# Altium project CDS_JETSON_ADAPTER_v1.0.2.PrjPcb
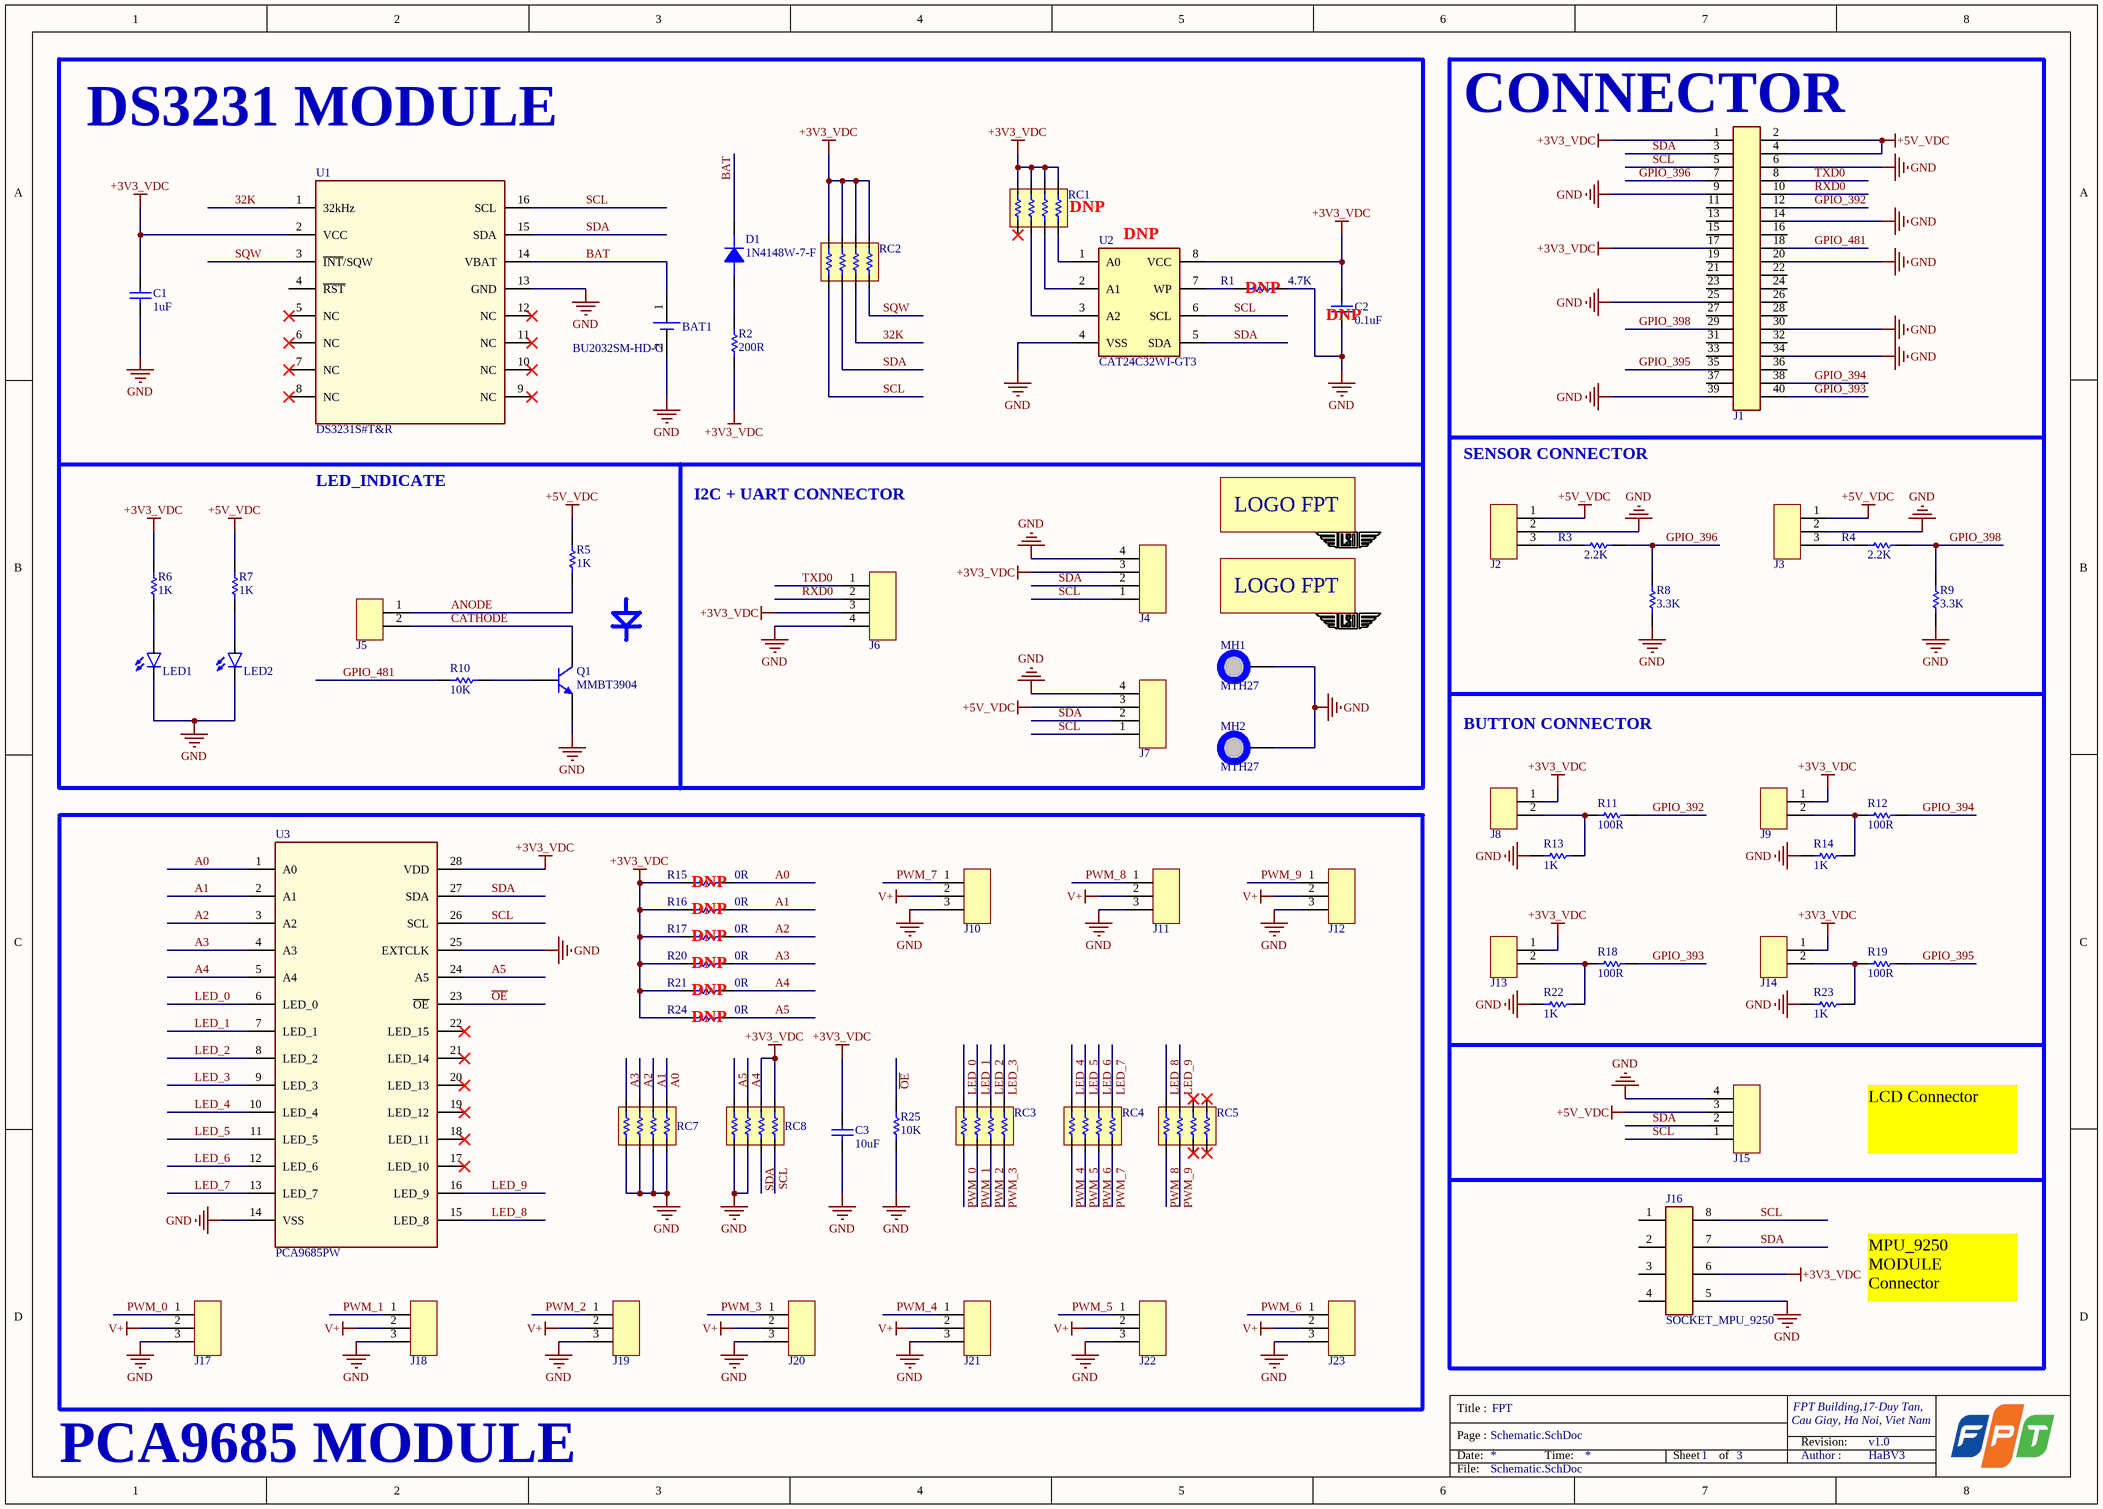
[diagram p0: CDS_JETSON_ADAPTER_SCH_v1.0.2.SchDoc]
1 sheet, 70 parts. Net scope: global (net labels, ports and power ports of the same name join across sheets).
Board file: CDS_JETSON_ADAPTER_PCB_v1.0.2.PcbDoc

## Sheet CDS_JETSON_ADAPTER_SCH_v1.0.2.SchDoc
size A3; Author: HaBV3; CompanyName: FPT CORPORATION; Address1: FPT Building,17-Duy Tan,; Address2: Cau Giay, Ha Noi, Viet Nam; Revision: v1.0; SheetNumber: 1; SheetTotal: 3; Project: FPT

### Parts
BAT1  BU2032SM-HD-G  [BU2032SM-HD-G]
C1  value 1uF  [C0603]  (hidden comment: GRM188R61A106ME69D)
C2  value 0.1uF  [C0603]  (hidden comment: GRM188R70J104KA01D)
C3  value 10uF  [C0603]  (hidden comment: GRM188R61C106KAALD)
D1  1N4148W-7-F  [DO-SOD-123]
J1  HDR_2x20  [HEADER_SOCKET_2.54MM_2x20]  (value not drawn)
J2  HDR_1x3  [B3B-XH-A(LF)(SN)]  (value not drawn)
J3  HDR_1x3  [B3B-XH-A(LF)(SN)]  (value not drawn)
J4  HDR_1x4  [B4B-XH-A(LF)(SN)]  (value not drawn)
J5  HDR_1x2  [B2B-XH-A(LF)(SN)]  (value not drawn)
J6  HDR_1x4  [B4B-XH-A(LF)(SN)]  (value not drawn)
J7  HDR_1x4  [B4B-XH-A(LF)(SN)]  (value not drawn)
J8  HDR_1x2  [B2B-XH-A(LF)(SN)]  (value not drawn)
J9  HDR_1x2  [B2B-XH-A(LF)(SN)]  (value not drawn)
J10  HDR_1x3  [PINHEAD_2.54mm_1x3]  (value not drawn)
J11  HDR_1x3  [PINHEAD_2.54mm_1x3]  (value not drawn)
J12  HDR_1x3  [PINHEAD_2.54mm_1x3]  (value not drawn)
J13  HDR_1x2  [B2B-XH-A(LF)(SN)]  (value not drawn)
J14  HDR_1x2  [B2B-XH-A(LF)(SN)]  (value not drawn)
J15  HDR_1x4  [B4B-XH-A(LF)(SN)]  (value not drawn)
J16  SOCKET_MPU_9250  [SOCKET_MPU_9250]
J17  HDR_1x3  [PINHEAD_2.54mm_1x3]  (value not drawn)
J18  HDR_1x3  [PINHEAD_2.54mm_1x3]  (value not drawn)
J19  HDR_1x3  [PINHEAD_2.54mm_1x3]  (value not drawn)
J20  HDR_1x3  [PINHEAD_2.54mm_1x3]  (value not drawn)
J21  HDR_1x3  [PINHEAD_2.54mm_1x3]  (value not drawn)
J22  HDR_1x3  [PINHEAD_2.54mm_1x3]  (value not drawn)
J23  HDR_1x3  [PINHEAD_2.54mm_1x3]  (value not drawn)
LED1  LTST-C191KRKT  [LED-SMD-0603-RED]  (value not drawn)
LED2  LTST-C191KRKT  [LED-SMD-0603-RED]  (value not drawn)
LOGO1  LOGOFPT  [LOGO_FPT]  (value not drawn)
LOGO2  LOGOFPT  [LOGO_FPT]  (value not drawn)
MH1  MTH27  [MH_5.2MMD_2.7MMD]
MH2  MTH27  [MH_5.2MMD_2.7MMD]
Q1  MMBT3904  [MMBT3904]
R1  value 4.7K  [R0603]  (hidden comment: RC0603JR-074K7L)
R2  value 200R  [R0603]  (hidden comment: RC0603JR-07200RL)
R3  value 2.2K  [R0603]  (hidden comment: RC0603FR-072K2L)
R4  value 2.2K  [R0603]  (hidden comment: RC0603FR-072K2L)
R5  value 1K  [R0603]  (hidden comment: RC0603FR-071KL)
R6  value 1K  [R0603]  (hidden comment: RC0603FR-071KL)
R7  value 1K  [R0603]  (hidden comment: RC0603FR-071KL)
R8  value 3.3K  [R0603]  (hidden comment: RC0603FR-073K3L)
R9  value 3.3K  [R0603]  (hidden comment: RC0603FR-073K3L)
R10  value 10K  [R0603]  (hidden comment: RC0603JR-0710KL)
R11  value 100R  [R0603]  (hidden comment: RC0603FR-07100RL)
R12  value 100R  [R0603]  (hidden comment: RC0603FR-07100RL)
R13  value 1K  [R0603]  (hidden comment: RC0603FR-071KL)
R14  value 1K  [R0603]  (hidden comment: RC0603FR-071KL)
R15  value 0R  [R0603]  (hidden comment: RC0603JR-070RL)
R16  value 0R  [R0603]  (hidden comment: RC0603JR-070RL)
R17  value 0R  [R0603]  (hidden comment: RC0603JR-070RL)
R18  value 100R  [R0603]  (hidden comment: RC0603FR-07100RL)
R19  value 100R  [R0603]  (hidden comment: RC0603FR-07100RL)
R20  value 0R  [R0603]  (hidden comment: RC0603JR-070RL)
R21  value 0R  [R0603]  (hidden comment: RC0603JR-070RL)
R22  value 1K  [R0603]  (hidden comment: RC0603FR-071KL)
R23  value 1K  [R0603]  (hidden comment: RC0603FR-071KL)
R24  value 0R  [R0603]  (hidden comment: RC0603JR-070RL)
R25  value 10K  [R0603]  (hidden comment: RC0603JR-0710KL)
RC1  YC164-JR-074K7L  [RC_1206]  (value not drawn)
RC2  YC164-JR-074K7L  [RC_1206]  (value not drawn)
RC3  YC164-JR-07220RL  [RC_1206]  (value not drawn)
RC4  YC164-JR-07220RL  [RC_1206]  (value not drawn)
RC5  YC164-JR-07220RL  [RC_1206]  (value not drawn)
RC7  YC164-JR-0710KL  [RC_1206]  (value not drawn)
RC8  YC164-JR-0710KL  [RC_1206]  (value not drawn)
U1  DS3231S#T&R  [SOIC127P1030X265-16N]
U2  CAT24C32WI-GT3  [SOIC127P600X175-8N]
U3  PCA9685PW  [TSOP65P640X110-28N]

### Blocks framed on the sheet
DS3231 MODULE: BAT1 C1 C2 D1 J4-J7 LED1 LED2 LOGO1 LOGO2 MH1 MH2 Q1 R1 R2 R5-R7 R10 RC1 RC2 U1 U2
CONNECTOR: J1-J3 J8 J9 J13-J16 R3 R4 R8 R9 R11-R14 R18 R19 R22 R23

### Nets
+3V3_VDC: C1.1 C2.2 C3.1 J1.1 J1.17 J4.3 J6.3 J8.1 J9.1 J13.1 J14.1 J16.6 R2.1 R6.1 R15.1 R16.1 R17.1 R20.1 R21.1 R24.1 RC1.5 RC1.6 RC1.7 RC1.8 RC2.5 RC2.6 RC2.7 RC2.8 RC8.5 RC8.6 U1.2(VCC) U2.8(VCC) U3.28(VDD)
+5V_VDC: J1.2 J1.4 J2.1 J3.1 J7.3 J15.3 R5.1 R7.1
GND: BAT1.2(-) C1.2 C2.1 C3.2 J1.6 J1.9 J1.14 J1.20 J1.25 J1.30 J1.34 J1.39 J2.2 J3.2 J4.4 J6.4 J7.4 J10.3 J11.3 J12.3 J15.4 J16.5 J17.3 J18.3 J19.3 J20.3 J21.3 J22.3 J23.3 LED1.C LED2.C MH1.1 MH2.1 Q1.2(E) R1.2 R8.2 R9.2 R13.2 R14.2 R22.2 R23.2 R25.2 RC7.1 RC7.2 RC7.3 RC7.4 RC8.1 RC8.2 U1.13(GND) U2.4(VSS) U3.14(VSS) U3.25(EXTCLK)
V+: J10.2 J11.2 J12.2 J17.2 J18.2 J19.2 J20.2 J21.2 J22.2 J23.2
32K: RC2.3 U1.1(32kHz)
~{OE}: R25.1 U3.23(~{OE})
A0: R15.2 RC7.5 U3.1(A0)
A1: R16.2 RC7.6 U3.2(A1)
A2: R17.2 RC7.7 U3.3(A2)
A3: R20.2 RC7.8 U3.4(A3)
A4: R21.2 RC8.7 U3.5(A4)
A5: R24.2 RC8.8 U3.24(A5)
ANODE: J5.1 R5.2
BAT: BAT1.1(+) D1.1(CATHODE) U1.14(VBAT)
CATHODE: J5.2 Q1.3(C)
GPIO_392: J1.12 R11.2
GPIO_393: J1.40 R18.2
GPIO_394: J1.38 R12.2
GPIO_395: J1.35 R19.2
GPIO_396: J1.7 R3.2 R8.1
GPIO_398: J1.29 R4.2 R9.1
GPIO_481: J1.18 R10.1
LED_0: RC3.8 U3.6(LED_0)
LED_1: RC3.7 U3.7(LED_1)
LED_2: RC3.6 U3.8(LED_2)
LED_3: RC3.5 U3.9(LED_3)
LED_4: RC4.8 U3.10(LED_4)
LED_5: RC4.7 U3.11(LED_5)
LED_6: RC4.6 U3.12(LED_6)
LED_7: RC4.5 U3.13(LED_7)
LED_8: RC5.8 U3.15(LED_8)
LED_9: RC5.7 U3.16(LED_9)
PWM_0: J17.1 RC3.1
PWM_1: J18.1 RC3.2
PWM_2: J19.1 RC3.3
PWM_3: J20.1 RC3.4
PWM_4: J21.1 RC4.1
PWM_5: J22.1 RC4.2
PWM_6: J23.1 RC4.3
PWM_7: J10.1 RC4.4
PWM_8: J11.1 RC5.1
PWM_9: J12.1 RC5.2
RXD0: J1.10 J6.2
SCL: J1.5 J4.1 J7.1 J15.1 J16.8 RC2.1 RC8.4 U1.16(SCL) U2.6(SCL) U3.26(SCL)
SDA: J1.3 J4.2 J7.2 J15.2 J16.7 RC2.2 RC8.3 U1.15(SDA) U2.5(SDA) U3.27(SDA)
SQW: RC2.4 U1.3(~{INT}/SQW)
TXD0: J1.8 J6.1
NetD1_2: D1.2(ANODE) R2.2
NetJ2_3: J2.3 R3.1
NetJ3_3: J3.3 R4.1
NetJ8_2: J8.2 R11.1 R13.1
NetJ9_2: J9.2 R12.1 R14.1
NetJ13_2: J13.2 R18.1 R22.1
NetJ14_2: J14.2 R19.1 R23.1
NetLED1_A: LED1.A R6.2
NetLED2_A: LED2.A R7.2
NetQ1_1: Q1.1(B) R10.2
NetR1_1: R1.1 U2.7(WP)
NetRC1_2: RC1.2 U2.3(A2)
NetRC1_3: RC1.3 U2.2(A1)
NetRC1_4: RC1.4 U2.1(A0)

Not connected (* = marked no-connect by the designer): J1 11 13 15 16 19 21 22 23 24 26 27 28 31 32 33 36 37; J16 1 2 3 4; RC1 1*; RC5 3* 4* 5* 6*; U1 4(~{RST}) 5(NC)* 6(NC)* 7(NC)* 8(NC)* 9(NC)* 10(NC)* 11(NC)* 12(NC)*; U3 17(LED_10)* 18(LED_11)* 19(LED_12)* 20(LED_13)* 21(LED_14)* 22(LED_15)*

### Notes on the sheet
- (near RC1) DNP
- (near U2) DNP
- (near R1) DNP
- (near C2) DNP
- LED_INDICATE
- I2C + UART CONNECTOR
- SENSOR CONNECTOR
- BUTTON CONNECTOR
- (near R15) DNP
- (near R16) DNP
- (near R17) DNP
- (near R20) DNP
- (near R21) DNP
- (near R24) DNP
- LCD Connector
- MPU_9250 MODULE Connector
- PCA9685 MODULE

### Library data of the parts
BAT1 = BU2032SM-HD-G: =Description; Part Name: Battery Holder; Manufacturer Part Description: HOLDER COIN CELL 2032 SMD; Manufacturer Name: MPD; Battery Type: Coin Cell, Holder; Style: Holder; Battery Cell Size: Coin, 20mm; Battery Series: 2032
C1 = GRM188R61A106ME69D: CAP CER 10UF 10V X5R 0603; Part Name: CAP-CERAMIC-0603; Manufacturer Name: Murata; Tolerance: ±20%
C2 = GRM188R70J104KA01D: CAP CER 0.1UF 6.3V X7R 0603; Part Name: CAP-CERAMIC-0603; Manufacturer Name: Murata; Tolerance: 10%
C3 = GRM188R61C106KAALD: CAP CER 10UF 16V X5R 0603; Part Name: CAP-CERAMIC-0603; Manufacturer Name: Murata; Tolerance: ±10%
D1 = 1N4148W-7-F: DIODE GEN PURP 100V 300MA SOD123; Manufacturer Name: Diodes Incorporated; Type: Standard; Current Average Rectified (Io): 300mA (DC); Voltage Forward (Vf) (Max): 1.25V @ 150mA; Reverse Recovery Time (trr): 4ns; Current Reverse Leakage @ Vr: 1µA @ 75V; Capacitance: 2pF @ 0V, 1MHz
J1 = SSW-120-03-G-D: CONN RCPT .100" 40POS DUAL GOLD; Manufacturer Name: Samtec Inc.; Connector Type: Receptacle; Number of Positions/Contacts: 40
J2 J3 = B3B-XH-A(LF)(SN): Connector Type: Header
J4 J6 J7 J15 = B4B-XH-A(LF)(SN): CONN HEADER XH TOP 4POS 2.5MM; Manufacturer Name: JST Sales America Inc.; Number of Positions/Contacts: 4
J5 J8 J9 J13 J14 = B2B-XH-A(LF)(SN): CONN HEADER XH TOP 2POS 2.5MM; Manufacturer Name: JST Sales America Inc; Connector Type: Header, Shrouded; Number of Positions/Contacts: 2
J10-J12 J17-J23 = 61300311121: CONN HEADER 3 POS 2.54; Manufacturer Name: Wurth Electronics Inc.; Number of Positions/Contacts: 3
J16 = MPU_9250
LED1 LED2 = LTST-C191KRKT: LED RED CLEAR 0603 SMD; Part Name: LED-SMD-1608-55; Manufacturer Name: Lite-One Inc.; Lens Color: Colorless; Millicandela Rating: 54mcd; Lens Style/Size: Rectangle with Flat Top, 1.10mm x 0.80mm; Voltage - Forward (Vf) (Typ): 2V; Current - Test: 20mA; Viewing Angle: 130°; Wavelength - Dominant: 631nm; Wavelength - Peak: 639nm
LOGO1 LOGO2 = LOGO-FPT: =Description; Part Name: LOGO; Manufacturer Part Description: FPT Logo
MH1 MH2 = MTH27: =Description; Manufacturer Part Description: Mouting Hole 2.7mm
Q1 = MMBT3904: TRANS NPN 40V 0.2A SOT23; Part Name: TRANS-NPN; Manufacturer Name: Fairchild/ON Semiconductor; Frequency - Transition: 350mW
R1 = RC0603JR-074K7L: RES SMD 4.7K OHM 5% 1/10W 0603; Manufacturer Name: Yageo; Rated Power: 0.1W
R2 = RC0603JR-07200RL: RES SMD 200 OHM 5% 1/10W 0603; Manufacturer Name: Yageo; Rated Power: 0.1W
R3 R4 = RC0603FR-072K2L: RES SMD 2.2K OHM 1% 1/10W 0603; Manufacturer Name: Yageo; Rated Power: 0.063W
R5-R7 R13 R14 R22 R23 = RC0603FR-071KL: RES SMD 1K OHM 1% 1/10W 0603; Manufacturer Name: Yageo; Rated Power: 0.15W
R8 R9 = RC0603FR-073K3L: RES SMD 3.3K OHM 1% 1/10W 0603; Manufacturer Name: Yageo; Rated Power: 0.1W
R10 R25 = RC0603JR-0710KL: RES SMD 10K OHM 5% 1/10W 0603; Manufacturer Name: Yageo; Rated Power: 0.1W
R11 R12 R18 R19 = RC0603FR-07100RL: RES SMD 100 OHM 1% 1/10W 0603; Manufacturer Name: Yageo; Rated Power: 0.15W
R15-R17 R20 R21 R24 = RC0603JR-070RL: RES SMD 0.0OHM JUMPER 1/10W 0603; Manufacturer Name: Yageo; Tolerance: 1%; Rated Power: 0.15W
RC1 RC2 = YC164-JR-074K7L: RES ARRAY 4 RES 4.7K OHM 1206; Manufacturer Name: Yageo; Tolerance: ±5%; Rated Power: 0.1W
RC3-RC5 = YC164-JR-07220RL: RES ARRAY 4 RES 220 OHM 1206; Manufacturer Name: Yageo; Value: 220R; Tolerance: ±5%; Rated Power: 0.1W
RC7 RC8 = YC164-JR-0710KL: RES ARRAY 4 RES 10K OHM 1206; Manufacturer Name: Yageo; Tolerance: ±5%; Rated Power: 0.1W
U1 = DS3231S#T&R: IC RTC CLK/CALENDAR I2C 16-SOIC; Manufacturer Name: Maxim; Time Format: HH:MM:SS (12/24 hr); Date Format: YY-MM-DD-dd; Interface: I²C, 2-Wire Serial; Voltage - Supply: 2.3 V ~ 5.5 V; Current - Timekeeping (Max): 110µA ~ 170µA @ 3.63V ~ 5.5V
U2 = CAT24C32WI-GT3: IC EEPROM 32K I2C 1MHZ 8SOIC; Manufacturer Name: ON Semiconductor; Memory Type: Non-Volatile; Memory Size: 32Kb(4Kx8); Voltage Supply: 1.7 V ~ 5.5 V
U3 = PCA9685PW: IC LED DRIVER RGBA 28-TSSOP; Manufacturer Name: NXP USA Inc.; Manufacturer Part Number: PCA9685PW,118; Internal Switch(s): Yes; Number of Outputs: 16; Voltage - Supply (Min): 2.3V; Voltage - Supply (Max): 5.5V; Current - Output / Channel: 25mA; Dimming: PWM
